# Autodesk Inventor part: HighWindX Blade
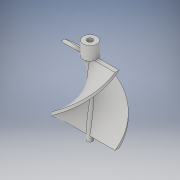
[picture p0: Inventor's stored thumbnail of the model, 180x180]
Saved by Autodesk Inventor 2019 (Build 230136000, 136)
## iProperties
Created: 2018-12
Part Number: HighWindX Blade
Material: PVC-Piping
Document SubType Name: Modeling
Designer: Patel Family
Density: 1.4 g/cm^3
Appearance: Default
Author: Patel Family
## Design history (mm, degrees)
sketch "Sketch1"
  geometry: L1 (-10, -0.75)-(10, -0.75); L2 (10, -0.75)-(10, 0.75); L3 (10, 0.75)-(-10, 0.75); L4 (-10, 0.75)-(-10, -0.75); L5 (-10, -0.75)-(10, 0.75); L6 (10, -0.75)-(-10, 0.75); 1 further point
  constraints: 12 end point, 2 midpoint, 2 parallel, 1 horizontal, 1 perpendicular
  dimensions: "d0" = 20 distance of L3.end L2.end; "d1" = 1.5 distance of L2.end L1.end
sketch "Sketch2"
  geometry: L1 (0, 0)-(0.727, 0)
  constraints: 2 end point, 1 horizontal
coil "Coil1" sketch "Sketch1", "Sketch2" pitch "d2" = 50; turns "d4" = 0.5; dims "d3" = 10, "d5" = 0, angle "d6" = 90 deg, angle "d7" = 90 deg, "d8" = 0, "d9" = 0
sketch "Sketch3"
  geometry: C1 r 2.5 at (10, -0.75); 1 further point
  constraints: 1 centre point, 1 coincident
  dimensions: "d10" = 5 diameter of C1
extrude "Extrusion1" join sketch "Sketch3" distance "d11" = 5; taper "d12" = 0 deg
sketch "Sketch4"
  geometry: C1 r 1 at (0, 0); 1 further point
  constraints: 1 centre point, 1 coincident
  dimensions: "d13" = 2 diameter of C1
extrude "Extrusion2" cut sketch "Sketch4" distance "d14" = 3; taper "d15" = 0 deg
sketch "Sketch5"
  geometry: C1 r 1 at (10, 0.75) reference; C2 r 1 at (10, 0.75); 1 further point
  constraints: 1 centre point, 1 coincident
extrude "Extrusion3" join sketch "Sketch5" distance "d16" = 27; taper "d17" = 0 deg
body "Solid1"
